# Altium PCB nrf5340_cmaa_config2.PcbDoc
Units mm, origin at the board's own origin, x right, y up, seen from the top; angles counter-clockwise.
Board outline 14 x 12 mm, 4 copper layers (Top Layer, Mid Layer 1, Mid Layer 2, Bottom Layer), stack 1.583 mm thick; 30 components, 69 nets, 170 pads, 84 vias.
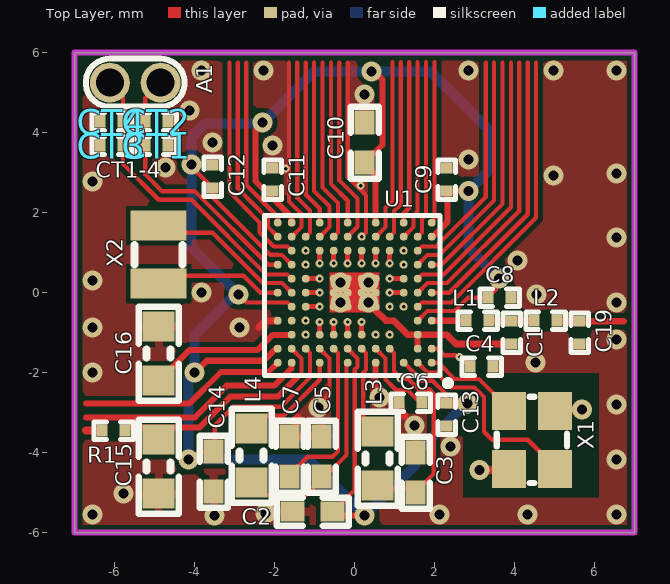
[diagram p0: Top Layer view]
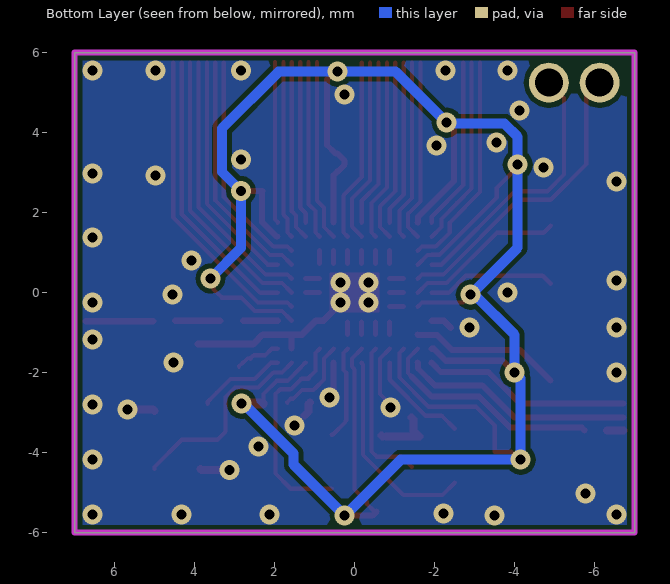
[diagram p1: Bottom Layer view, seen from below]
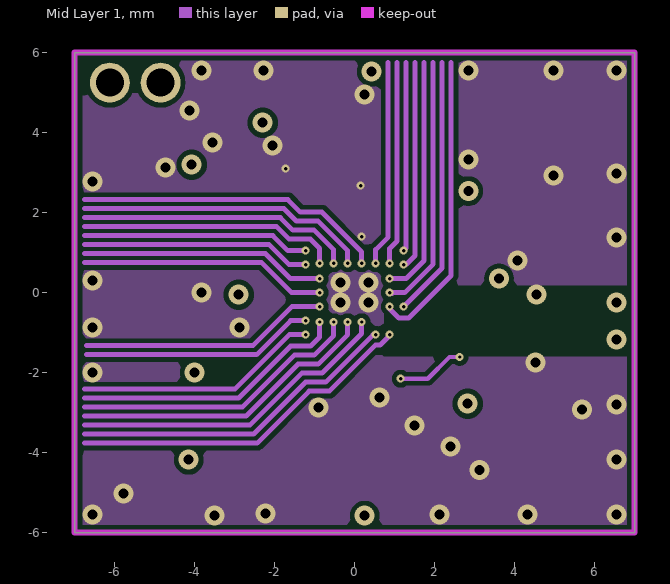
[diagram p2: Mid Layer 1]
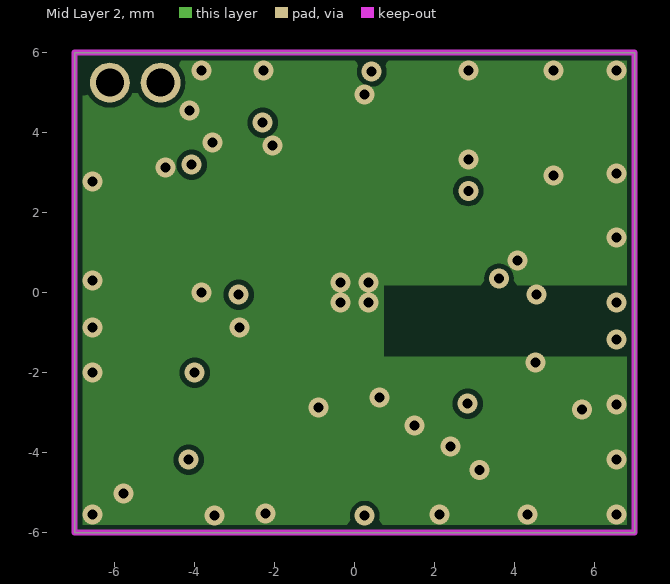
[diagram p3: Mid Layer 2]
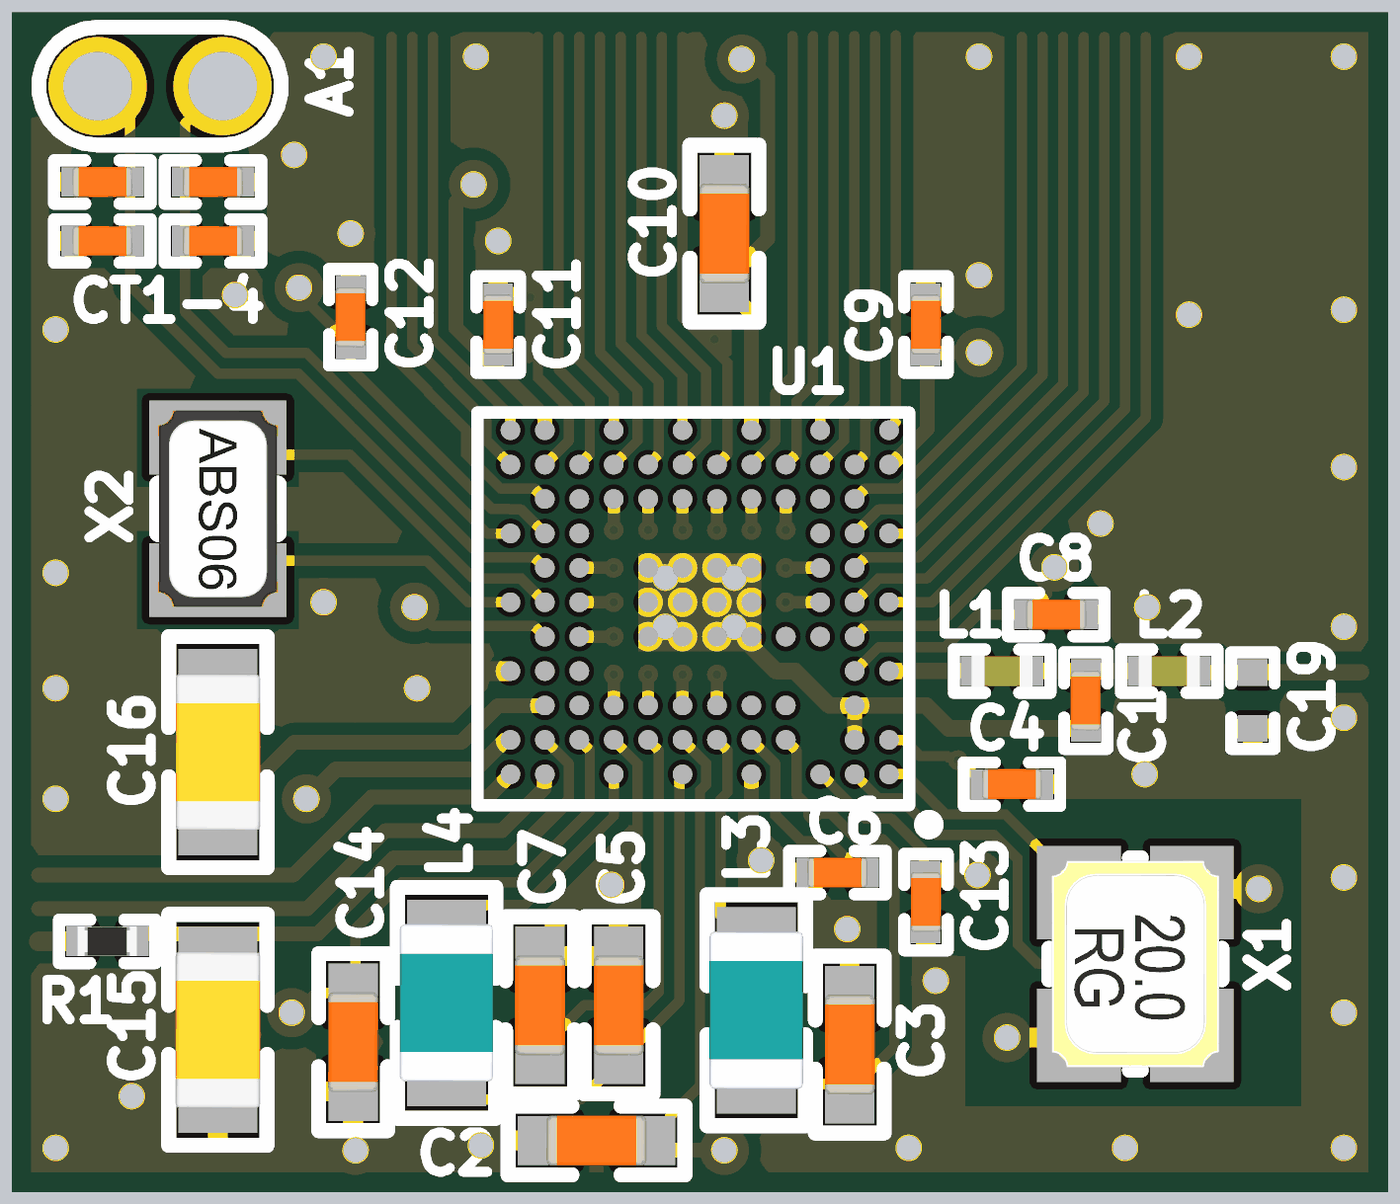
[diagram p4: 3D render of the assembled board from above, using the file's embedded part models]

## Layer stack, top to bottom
Top Solder: solder mask 0.0102, Solder Resist, Dk 3.5
Top Layer: signal copper 0.0356
Dielectric1: core 0.07, FR-4, Dk 4.8
Mid Layer 1: signal copper 0.036
Dielectric 3: prepreg 1.3, Dk 4.2
Mid Layer 2: signal copper 0.036
Dielectric 2: core 0.07, Dk 4.2
Bottom Layer: signal copper 0.0356
Bottom Solder: solder mask 0.0102, Solder Resist, Dk 3.5

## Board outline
-7,-6 7,-6 7,6 -7,6

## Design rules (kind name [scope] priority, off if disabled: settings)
Clearance Clearance_microvia [AsMM(ViaDiameter) = 0.3 vs AsMM(ViaDiameter) = 0.3] p1: gap=0.1 ignorepadtopadclearanceinfootprint=FALSE
Clearance Polygon_ANT [(InNamedPolygon('Top_Layer-GND')) or  (InNamedPolygon('Mid_Layer_1-GND')) or (InNamedPolygon('Mid_Layer_2-GND')) or (InNamedPolygon('Bottom_Layer-GND')) vs InNet('RF')] p2: gap=0.127 ignorepadtopadclearanceinfootprint=FALSE except(0: Arc-Hole Track-Hole SMDPad-Hole THPad-Hole Via-Hole Fill-Hole Poly-Hole Region-Hole Text-Hole)
Clearance Polygon [(InNamedPolygon('Top_Layer-GND')) or  (InNamedPolygon('Mid_Layer_1-GND')) or (InNamedPolygon('Mid_Layer_2-GND')) or (InNamedPolygon('Bottom_Layer-GND'))] p3: gap=0.125 ignorepadtopadclearanceinfootprint=FALSE
Clearance Clearance_Top [OnTopLayer] p4: gap=0.09 ignorepadtopadclearanceinfootprint=FALSE
Clearance [All] p5: gap=0.1 ignorepadtopadclearanceinfootprint=FALSE
ComponentClearance [All] p1 off: gap=0.254 collisioncheckmode=3 verticalgap=0.254 showdistances=FALSE
DiffPairsRouting [All] p1: maxlimit=0.193 minlimit=0.193 mostfreqgap=0.193 toplayer_minwidth=0.125 toplayer_maxwidth=0.381 toplayer_prefwidth=0.165 midlayer1_minwidth=0.125 midlayer1_maxwidth=0.381 midlayer1_prefwidth=0.165 midlayer2_minwidth=0.125 midlayer2_maxwidth=0.381 midlayer2_prefwidth=0.165 bottomlayer_minwidth=0.125 bottomlayer_maxwidth=0.381 bottomlayer_prefwidth=0.165 maxuncoupledlength=12.7
FabricationTestPointUsage TestPointUsage [All] p1: valid=0 allowmultiple=FALSE
FabricationTestpoint Testpoint [All] p1: side=3 testpointundercomponent=TRUE minsize=1.016 maxsize=2.54 preferedsize=1.524 minholesize=0 maxholesize=1.016 preferedholesize=0.813 testpointgrid=0.025 allowsidetop=TRUE allowsidebottom=TRUE usegrid=TRUE gridtolerance=0
Height [All] p1 off: minheight=0 maxheight=25.4 prefheight=12.7
HoleSize [All] p1: absolutevalues=TRUE maxlimit=4.064 minlimit=0.08 maxpercent=80.000 minpercent=20.000
MinimumAnnularRing [All] p1 off: minimumring=0.152
PolygonConnect PolygonConnect_1 [isVia and innet(gnd)] p1: connectstyle=Direct reliefconductorwidth=0.254 reliefentries=4 polygonreliefangle="90 Angle" airgapwidth=0.254
PolygonConnect [All] p2: connectstyle=Relief reliefconductorwidth=0.2 reliefentries=4 polygonreliefangle="90 Angle" airgapwidth=0.125
RoutingVias [All] p1: holewidth=0.1 width=0.25 viastyle="Through Hole" minholewidth=0.1 minwidth=0.25 maxholewidth=0.25 maxwidth=0.5 useviatemplates=TRUE viatemplateguid#1={ABB39D13-3140-4941-832D-BD17CF3CD9F1} viatemplateguid#2={15471998-75C1-4FB5-9936-6AB580A247F9} viatemplatename#1=v20h8m0 viatemplatename#2=v50h25m0mx0
SilkToSolderMaskClearance SilkscreenOverComponentPads [IsPad] p1: minsilkscreentomaskgap=0.254 clearancetoexposedcopper=TRUE
SolderMaskExpansion SolderMaskExpansion_via [isVia] p1: expansion=0.076 istentingtop=TRUE
SolderMaskExpansion [All] p2: expansion=0.076 istentingtop=FALSE
Width [All] p1: maxlimit=2 minlimit=0.105 preferedwidth=0.125 minimp=50.000000 maximp=50.000000 favimp=50.000000
23 further rules are at their usual default settings.

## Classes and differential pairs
differential pair D: +D_P -D_N

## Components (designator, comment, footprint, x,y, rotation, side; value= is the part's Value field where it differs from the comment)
A1 "NFC Antenna" TP_2x1mm_TH -5.488,5.25 r270 top
C1 "0.7pF" CAPC0603X03L_C#1 3.925,-1 r90 top
C2 "1.0µF" CAPC1005X04L -1.05,-5.475 r180 top
C3 "1.0µF" CAPC1005X04L 1.525,-4.5 r270 top
C4 "2.2nF" CAPC0603X03L_C#1 3.175,-1.85 r0 top
C5 "1.0µF" CAPC1005X04L -0.825,-4.1 r270 top
C6 "100nF" CAPC0603X03L_C#1 1.4,-2.75 r180 top
C7 "1.0µF" CAPC1005X04L -1.625,-4.1 r270 top
C8 "100nF" CAPC0603X03L_C#1 3.625,-0.125 r0 top
C9 "100nF" CAPC0603X03L_C#1 2.3,2.825 r90 top
C10 "1.0µF" CAPC1005X04L 0.25,3.75 r90 top
C11 "100nF" CAPC0603X03L_C#2 -2.05,2.825 r90 top
C12 "100nF" CAPC0603X03L_C#1 -3.55,2.9 r90 top
C13 "100nF" CAPC0603X03L_C#1 2.3,-3.05 r270 top
C14 "1.0µF" CAPC1005X04L -3.525,-4.475 r90 top
C15 "4.7µF" CAPC1608X06L -4.9,-4.35 r270 top
C16 "4.7µF" CAPC1608X06L -4.9,-1.525 r90 top
C19 "N.C." CAPC0603X03L_C_NC 5.625,-1 r90 top
CT1 "Antenna dependent" CAPC0603X03L_C#2 -4.95,3.675 r0 top
CT2 "Antenna dependent" CAPC0603X03L_C#2 -4.95,4.275 r0 top
CT3 "Antenna dependent" CAPC0603X03L_C#2 -6.075,3.675 r0 top
CT4 "Antenna dependent" CAPC0603X03L_C#2 -6.075,4.275 r0 top
L1 "2.2nH" INDC0603X03L_C 3.075,-0.7 r180 top
L2 "2.2nH" INDC0603X03L_C 4.775,-0.7 r180 top
L3 "10µH" INDC1608X06L 0.575,-4.15 r90 top
L4 "10µH" INDC1608X06L -2.575,-4.075 r90 top
R1 "2R2" RESC0603X03L_C -6.025,-3.45 r0 top
U1 "nRF5340-CMAA" BGA95C35P12X11_439X399X49 0,0 r180 top
X1 "32MHz" BT-XTAL_2016 4.43,-3.68 r270 top
X2 "32.768kHz" XTAL_2012 -4.9,0.95 r270 top

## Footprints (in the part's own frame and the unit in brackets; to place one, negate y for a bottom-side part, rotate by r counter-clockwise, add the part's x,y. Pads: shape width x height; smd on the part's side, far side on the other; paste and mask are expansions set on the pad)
BGA95C35P12X11_439X399X49 [mm] "BGA, 95-Leads, Body 4.39x3.99mmx0.49mm, Pitch 0.35mm"
  round 0.2 smd mask+0.05: A1(-1.925,1.75) A2(-1.575,1.75) A3(-1.225,1.75) A5(-0.525,1.75) A7(0.175,1.75) A9(0.875,1.75) A11(1.575,1.75) A12(1.925,1.75) B1(-1.925,1.4) B2(-1.575,1.4) B4(-0.875,1.4) B5(-0.525,1.4) B6(-0.175,1.4) B7(0.175,1.4) B8(0.525,1.4) B9(0.875,1.4) B10(1.225,1.4) B11(1.575,1.4) B12(1.925,1.4) C2(-1.575,1.05) C4(-0.875,1.05) C5(-0.525,1.05) C6(-0.175,1.05) C7(0.175,1.05) C8(0.525,1.05) C9(0.875,1.05) C10(1.225,1.05) C11(1.575,1.05) D1(-1.925,0.7) D2(-1.575,0.7) D10(1.225,0.7) D11(1.575,0.7) D12(1.925,0.7) E2(-1.575,0.35) E3(-1.225,0.35) E4(-0.875,0.35) E5(-0.525,0.35) E6(-0.175,0.35) E7(0.175,0.35) E8(0.525,0.35) E10(1.225,0.35) E11(1.575,0.35) F1(-1.925,0) F2(-1.575,0) F3(-1.225,0) F5(-0.525,0) F6(-0.175,0) F7(0.175,0) F8(0.525,0) F10(1.225,0) F11(1.575,0) F12(1.925,0) G2(-1.575,-0.35) G3(-1.225,-0.35) G5(-0.525,-0.35) G6(-0.175,-0.35) G7(0.175,-0.35) G8(0.525,-0.35) G10(1.225,-0.35) G11(1.575,-0.35) H1(-1.925,-0.7) H2(-1.575,-0.7) H3(-1.225,-0.7) H10(1.225,-0.7) H11(1.575,-0.7) H12(1.925,-0.7) J2(-1.575,-1.05) J3(-1.225,-1.05) J4(-0.875,-1.05) J5(-0.525,-1.05) J6(-0.175,-1.05) J7(0.175,-1.05) J8(0.525,-1.05) J9(0.875,-1.05) J10(1.225,-1.05) J11(1.575,-1.05) K1(-1.925,-1.4) K2(-1.575,-1.4) K3(-1.225,-1.4) K4(-0.875,-1.4) K5(-0.525,-1.4) K6(-0.175,-1.4) K7(0.175,-1.4) K8(0.525,-1.4) K9(0.875,-1.4) K10(1.225,-1.4) K11(1.575,-1.4) K12(1.925,-1.4) L1(-1.925,-1.75) L3(-1.225,-1.75) L5(-0.525,-1.75) L7(0.175,-1.75) L9(0.875,-1.75) L11(1.575,-1.75) L12(1.925,-1.75)
  silkscreen extent -2.38,-1.93 2.26,2.31, body extent -2.13,-1.93 2.26,2.06, height 0.41
BT-XTAL_2016 [mm] "Crystal 2.0 x 1.6 mm"
  rect 0.95x0.85 smd: 1(-0.725,-0.575) 2(0.725,-0.575) 3(0.725,0.575) 4(-0.725,0.575)
  silkscreen extent -1.08,-0.88 1.08,0.88, body extent -1.05,-0.85 1.05,0.85, height 0.56
CAPC0603X03L_C#1 [mm] "Chip Capacitor, 2-Leads, Body 0.6x0.3mm, IPC High Density"
  rect 0.27x0.3 smd: 1(-0.285,0) 2(0.285,0)
  silkscreen extent -0.49,-0.22 0.49,0.22, body extent -0.3,-0.15 0.31,0.15, height 0.3
CAPC0603X03L_C#2 [mm] "Chip Capacitor, 2-Leads, Body 0.6x0.3mm, IPC High Density"
  rect 0.27x0.3 smd mask+0.05: 1(-0.285,0) 2(0.285,0)
  silkscreen extent -0.49,-0.22 0.49,0.22, body extent -0.3,-0.15 0.31,0.15, height 0.3
CAPC0603X03L_C_NC [mm] "Chip Capacitor, 2-Leads, Body 0.6x0.3mm, IPC High Density"
  rect 0.27x0.3 smd mask+0.05: 1(-0.285,0) 2(0.285,0)
  silkscreen extent -0.49,-0.22 0.49,0.22
CAPC1005X04L [mm] "Chip Capacitor, 2-Leads, Body 1.0x0.5mm, IPC High Density"
  rect 0.6x0.5 smd: 1(-0.5,0) 2(0.5,0)
  silkscreen extent -0.9,-0.35 0.9,0.35, body extent -0.51,-0.25 0.51,0.25, height 0.5
CAPC1608X06L [mm] "Chip Capacitor, 2-Leads, Body 1.6x0.8mm, IPC High Density"
  rect 0.75x0.8 smd: 1(-0.675,0) 2(0.675,0)
  silkscreen extent -1.17,-0.5 1.17,0.5, body extent -0.8,-0.43 0.8,0.43, height 0.8
INDC0603X03L_C [mm] "Chip Inductor, 2-Leads, Body 0.6x0.3mm, IPC High Density"
  rect 0.27x0.3 smd: 1(-0.285,0) 2(0.285,0)
  silkscreen extent -0.49,-0.22 0.49,0.22, body extent -0.31,-0.16 0.31,0.16, height 0.26
INDC1608X06L [mm] "Chip Inductor, 2-Leads, Body 1.6x0.8mm, IPC High Density"
  rect 0.75x0.8 smd: 1(-0.675,0) 2(0.675,0)
  silkscreen extent -1.17,-0.5 1.17,0.5, body extent -0.8,-0.48 0.8,0.48, height 0.8
RESC0603X03L_C [mm] "Chip Resistor, 2-Leads, Body 0.6x0.3mm, IPC High Density"
  rect 0.27x0.3 smd: 1(-0.285,0) 2(0.285,0)
  silkscreen extent -0.49,-0.22 0.49,0.22, body extent -0.3,-0.15 0.3,0.15, height 0.23
TP_2x1mm_TH [mm]
  round 1 hole 0.7: 1(0,-0.635) 2(0,0.635)
  silkscreen extent -0.6,-1.23 0.6,1.23
XTAL_2012 [mm] "XTAL SMD 2.0 x 1.2 mm"
  rect 0.75x1.4 smd: 1(-0.725,0) 2(0.725,0)
  silkscreen extent -0.24,-0.6 0.24,0.6, body extent -1,-0.61 1,0.61, height 0.6

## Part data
A1: library part NFC_ANT_TP
C1: library part C0201-0.7p, "Capacitor, NP0, ±0.05pF"
C2 C3 C5 C7 C10 C14: library part C0402-1µ0-10V-X7S-GRM155C71A105KE11, "Capacitor, X7S, ±10%"
C4: library part C0201-2n2, "Capacitor, X7R, ±10%"
C6 C8 C9 C11 C12 C13: library part C0201-100n-16V-X7S, "Capacitor, X7S, ±10%"
C15: library part C0603-4µ7-10V-X7S, "Capacitor, X7S, ±10%"
C16: library part C0603-4µ7-6.3V-X7R, "Capacitor, X7R, ±10%"
C19: library part C0201-N.C., "Not mounted"
CT1 CT2 CT3 CT4: library part C0201-TBD, "Capacitor, NP0, ±5%"
L1 L2: library part L0201-2n2, "High frequency chip inductor, ±5%"
L3 L4: library part L0603-10µ, "Chip inductor, IDC,min = 50 mA, ±20%"
R1: library part R0201-2R2, "Resistor, ±1%, 0.05W"
U1: "Multi-protocol Bluetooth Low Energy, IEEE 802.15.4, ANT and 2.4GHz proprietary system-on-chip", Manufacturer="Nordic Semiconductor"
X1: library part XTAL_SMD2016_32MHz_8pF_General, "XTAL SMD 2016, 32MHz, Cl=8pF, Total Tol: ±30ppm"
X2: library part XTAL_SMD2012_32.768kHz_9pF_General, "XTAL SMD 2012, 32.768kHz, Cl=9pF, Total Tol: ±50ppm"

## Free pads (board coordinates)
  round 0.2 on Mech16: 1(-1.225,-1.05) 1(-1.225,-0.7) 1(-1.225,0.7) 1(-1.225,1.05) 1(0.175,1.4) 1(0.525,-1.05) 1(0.875,-1.05) 1(0.875,-0.35) 1(1.225,-0.35) 1(1.225,0.7) 1(1.225,1.05)
  round 0.5 on Mech16: 1(-0.35,-0.25) 1(-0.35,0.25) 1(0.35,0.25) 1(0.35,-0.25)

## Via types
v1: diameter 0.5, hole 0.25, Top Layer to Bottom Layer, tented both sides, 54 vias
v2: diameter 0.2, hole 0.08, Top Layer to Mid Layer 1, tented both sides, 30 vias

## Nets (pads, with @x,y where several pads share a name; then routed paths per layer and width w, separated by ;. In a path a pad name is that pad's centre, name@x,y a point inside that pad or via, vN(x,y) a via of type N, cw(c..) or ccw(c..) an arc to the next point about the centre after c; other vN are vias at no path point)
ANT: L1.2 U1.D1 | length 0.9
  Top Layer w0.165: U1.D1 L1.2@2.79,-0.7
D_N: U1.A11 | length 5.8
  Top Layer w0.15: -6.722,-3.118 -3.993,-3.118 -3.2,-2.325 -2.013,-2.325 -1.582,-1.894 -1.582,-1.771 -1.579,-1.768 -1.579,-1.754 U1.A11
D_P: U1.A12 | length 5.2
  Top Layer w0.15: -6.722,-2.775 -4.135,-2.775 -3.342,-1.982 -2.155,-1.982 -1.925,-1.752 U1.A12
GND: C1.1 C2.2 C3.1 C4.2 C5.1 C6.2 C7.1 C8.2 C9.2 C10.2 C11.2 C12.2 C13.2 C14.1 C15.2 C16.2 C19.1 CT1.2 CT2.2 CT3.1 CT4.1 U1.A5 U1.B2 U1.B9 U1.C2 U1.D12 U1.E5 U1.E6 U1.E7 U1.E8 U1.F5 U1.F6 U1.F7 U1.F8 U1.G5 U1.G6 U1.G7 U1.G8 U1.K6 U1.K11 X1.2 X1.4 | length 19.5
  Top Layer w0.105: -1.645,5.75 -1.645,2.284 -1.332,1.972 -1.332,1.643 U1.K11 ; v1@-0.9,-2.8 -0.632,-2.532 -0.632,-1.643 U1.B9 ; -0.175,5.75 -0.175,2.893 0.282,2.436 0.282,1.507 v2(0.175,1.4)
  Top Layer w0.15: v1@0.525,-2.515 U1.A5 ; U1.B2 U1.C2
  Top Layer w0.17: -2.4,-0.875 -2.225,-0.7 U1.D12 ; U1.E5 0.525,-0.445 0.78,-0.7 0.97,-0.7 1.32,-1.05 U1.C2 2.3,-1.05 2.535,-1.285 C1.1
  Top Layer w0.2: C7.1 -1.475,-3.45 -1.475,-3.175 -1.425,-3.125 ; C7.1@-1.6,-3.6 C5.1 C5.1@-0.8,-3.6 ; C5.1@-0.7,-3.6 C5.1@-0.675,-3.575 ; C6.2 1.15,-2.785 1.15,-2.975 1.25,-3.075 ; v1(3.125,-4.429) 3.832,-4.429 X1.2 ; X1.4 5.045,-2.915 v1(5.684,-2.915)
  other v1: -3.5,-5.575 -6.55,-5.55 2.125,-5.55 4.325,-5.55 6.55,-5.55 -2.225,-5.525 -5.775,-5.025 6.55,-4.175 2.4,-3.85 1.5,-3.325 -0.9,-2.875 6.55,-2.8 0.625,-2.625 -6.55,-2 4.525,-1.75 6.55,-1.175 -6.55,-0.875 -2.875,-0.875 -0.35,-0.25 0.35,-0.25 6.55,-0.25 4.55,-0.05 -3.825,0 -0.35,0.25 0.35,0.25 -6.55,0.3 4.075,0.8 6.55,1.375 -6.55,2.775 4.975,2.925 6.55,2.975 -4.725,3.125 2.84,3.325 -2.05,3.675 -3.55,3.75 -4.125,4.55 0.25,4.95 -3.825,5.55 -2.275,5.55 2.84,5.55 4.975,5.55 6.55,5.55
  other v2: 0.15,2.675 -1.725,3.1
NetC1_2: C1.2 L1.1 L2.2 | length 1.1
  Top Layer w0.165: L1.1 L2.2
NetC3_2: C3.2 C4.1 L3.1 U1.B1 U1.B4 | length 8.3
  Top Layer w0.105: L3.1@0.575,-4.9 1.6,-4.9 1.977,-4.523 1.977,-2.527 1.863,-2.413 1.598,-2.413 1.337,-2.152 v2@1.226,-2.152 ; U1.B4 0.982,-1.507 0.982,-1.775 0.982,-1.957 1.176,-2.15 1.224,-2.15 v2@1.226,-2.152 ; v2(1.15,-2.15) 1.152,-2.152 v2@1.226,-2.152 ; U1.B1 2.075,-1.4 2.24,-1.565 2.515,-1.565 2.529,-1.579 2.558,-1.579 2.6,-1.62 v2@2.6,-1.65 ; v2@2.683,-1.643 2.793,-1.753 2.808,-1.753 2.89,-1.835 C4.1
  Mid Layer 1 w0.105: v2(1.15,-2.15) 1.825,-2.15 2.369,-1.606 v2(2.625,-1.606)
NetC5_2: C5.2 L4.1 U1.A7 | length 5.2
  Top Layer w0.105: L4.1@-2.5,-4.75 -2.192,-5.058 -1.213,-5.058 -0.208,-4.052 -0.208,-1.8 -0.175,-1.768 U1.A7
NetC6_1: C6.1 U1.B5 | length 2
  Top Layer w0.105: U1.B5 0.768,-1.643 0.768,-2.167 0.988,-2.387 1.033,-2.432 1.321,-2.432 1.541,-2.653 1.602,-2.653 1.685,-2.735 C6.1
NetC7_2: C7.2 U1.B8 | length 3.8
  Top Layer w0.105: C7.2@-1.428,-4.353 -1.175,-4.1 -0.552,-4.1 -0.418,-3.965 -0.418,-1.507 U1.B8
NetC15_1: C15.1 R1.2 U1.B11 | length 5.7
  Top Layer w0.105: U1.B11 -1.332,-1.643 -1.332,-2.007 -1.425,-2.1
  Top Layer w0.15: R1.2 -5.74,-3.435 -5.68,-3.375 -5.665,-3.375 -5.663,-3.373 -3.885,-3.373 -3.112,-2.6 -1.925,-2.6 -1.425,-2.1
NetC16_1: C16.1 U1.C11 | length 3.8
  Top Layer w0.15: C16.1 -4.126,-1.426 -2.426,-1.426 -2.051,-1.051 U1.C11@-1.576,-1.051
NetL3_2: L3.2 U1.B6 | length 2.4
  Top Layer w0.105: U1.B6 0.282,-1.507 0.282,-1.932 0.213,-2.002 0.213,-3.188 0.227,-3.202 0.227,-3.227 0.55,-3.55 L3.2@0.575,-3.55
NetL4_2: L4.2 U1.A9 | length 2.6
  Top Layer w0.105: L4.2@-2.5,-3.4 -2.178,-3.077 -1.777,-3.077 -0.875,-2.176 U1.A9
P0.00/XL1: U1.F11 X2.1 | length 4
  Top Layer w0.105: X2.1 -4.725,1.5 -3.556,1.5 -2.298,0.243 -1.818,0.243 U1.F11
P0.01/XL2: U1.F12 X2.2 | length 3.2
  Top Layer w0.105: X2.2 -4.701,0.424 -2.776,0.424 -2.353,0 U1.F12
P0.02/NFC1: A1.1 CT3.2 CT4.2 U1.G11 | length 7.6
  Top Layer w0.105: A1.1 -5.79,4.917 CT4.2 CT3.2 -5.79,3.59 -5.79,3.215 -4.9,2.325 -4.084,2.325 -2.216,0.457 -2.025,0.457 -1.682,0.457 U1.G11
P0.03/NFC2: A1.2 CT1.1 CT2.1 U1.H12 | length 6.7
  Top Layer w0.105: A1.2 -5.235,4.868 CT2.1 CT1.1 -5.235,2.957 -4.813,2.535 -3.997,2.535 -2.162,0.7 U1.H12
P0.04/AIN0: U1.G10 | length 6.5
  Top Layer w0.125: U1.G10 v2(-0.875,0.35)
  Mid Layer 1 w0.125: -6.757,0.975 -2.232,0.975 -1.607,0.35 v2(-0.875,0.35)
P0.05/AIN1: U1.F10 | length 6.5
  Top Layer w0.125: U1.F10 v2(-0.875,0)
  Mid Layer 1 w0.125: -6.757,0.75 -2.325,0.75 -1.575,0 v2(-0.875,0)
P0.06/AIN2: U1.H10 | length 5.7
  Mid Layer 1 w0.125: -6.757,1.2 -2.139,1.2 -1.639,0.7 v2(-1.225,0.7)
P0.07/AIN3: U1.J10 | length 5.7
  Mid Layer 1 w0.125: -6.757,1.425 -2.045,1.425 -1.67,1.05 v2(-1.225,1.05)
P0.08/TRACEDATA3: U1.L12 | length 4.3
  Top Layer w0.105: -2.713,5.75 -2.713,2.694 -2.325,2.307 -2.325,2.3 -1.925,1.9 U1.L12
P0.09/TRACEDATA2: U1.J9 | length 6.8
  Top Layer w0.125: v2(-0.875,0.735) U1.J9
  Mid Layer 1 w0.125: -6.757,1.65 -1.952,1.65 -1.64,1.338 -1.106,1.338 -0.875,1.107 v2(-0.875,0.735)
P0.10/TRACEDATA1: U1.J8 | length 7.2
  Top Layer w0.125: v2(-0.525,0.735) U1.J8
  Mid Layer 1 w0.125: -6.757,1.875 -1.859,1.875 -1.547,1.563 -1.013,1.563 -0.525,1.075 v2(-0.525,0.735)
P0.11/TRACEDATA0: U1.J7 | length 7.6
  Top Layer w0.125: v2(-0.175,0.735) U1.J7
  Mid Layer 1 w0.125: -6.757,2.1 -1.766,2.1 -1.453,1.788 -0.912,1.788 -0.175,1.05 v2(-0.175,0.735)
P0.12/TRACECLK: U1.J6 | length 8.1
  Top Layer w0.125: v2(0.175,0.735) U1.J6
  Mid Layer 1 w0.125: -6.757,2.325 -1.673,2.325 -1.36,2.013 -0.819,2.013 0.175,1.018 v2(0.175,0.735)
P0.13/QSPI0: U1.K10 | length 4.5
  Top Layer w0.105: -1.435,5.75 -1.435,2.371 -1.118,2.054 -1.118,1.507 U1.K10
P0.14/QSPI1: U1.K9 | length 4.6
  Top Layer w0.105: -1.015,5.75 -1.015,2.545 -0.632,2.163 -0.632,1.643 U1.K9
P0.15/QSPI2: U1.L9 | length 4.1
  Top Layer w0.105: -1.225,5.75 -1.225,2.458 -0.875,2.108 U1.L9
P0.16/QSPI3: U1.K8 | length 4.6
  Top Layer w0.105: -0.805,5.75 -0.805,2.632 -0.418,2.245 -0.418,1.507 U1.K8
P0.17/QSPI_CLK: U1.L7 | length 4.2
  Top Layer w0.105: -0.595,5.75 -0.595,2.719 -0.175,2.299 U1.L7
P0.18/QSPI_CS: U1.K7 | length 4.6
  Top Layer w0.105: -0.385,5.75 -0.385,2.806 0.068,2.354 0.068,1.65 -0.175,1.407 U1.K7
P0.19: U1.J5 | length 5.5
  Top Layer w0.125: v2(0.525,0.735) U1.J5
  Mid Layer 1 w0.125: v2(0.525,0.735) 0.525,1.075 0.838,1.387 0.838,5.75
P0.20: U1.K5 | length 4.5
  Top Layer w0.105: U1.K5 0.768,1.643 0.768,2.123 0.943,2.298 0.943,5.759
P0.21: U1.J4 | length 5.4
  Top Layer w0.125: v2(0.875,0.735) U1.J4
  Mid Layer 1 w0.125: v2(0.875,0.735) 0.875,1.107 1.063,1.294 1.063,5.75
P0.22: U1.K4 | length 4.5
  Top Layer w0.105: U1.K4 0.982,1.507 0.982,2.041 1.153,2.211 1.153,5.759
P0.23: U1.H3 | length 5.2
  Mid Layer 1 w0.125: v2(1.225,0.7) 1.282,0.7 1.513,0.931 1.513,5.75
P0.24: U1.K2 | length 4.4
  Top Layer w0.105: U1.K2 1.682,1.507 1.682,1.85 1.783,1.95 1.783,5.759
P0.25/AIN4: U1.L1 | length 4
  Top Layer w0.105: U1.L1 1.925,1.768 1.993,1.835 1.993,5.765
P0.26/AIN5: U1.J2 | length 5.6
  Top Layer w0.105: U1.J2 1.682,1.157 2.036,1.157 3.275,2.396 3.275,5.75
P0.27/AIN6: U1.H1 | length 5.9
  Top Layer w0.105: U1.H1 2.173,0.7 3.695,2.222 3.695,5.75
P0.28/AIN7: U1.E3 | length 6.5
  Mid Layer 1 w0.125: v2(1.225,-0.35) 1.225,-0.343 2.188,0.62 2.188,5.75
P0.29: U1.E2 | length 7.8
  Top Layer w0.105: U1.E2 1.682,-0.243 2.418,-0.243 4.535,1.875 4.535,5.75
P0.30: U1.C4 | length 8.8
  Mid Layer 1 w0.125: -6.757,-3.762 -2.438,-3.762 -1.138,-2.463 -0.633,-2.463 0.517,-1.313 0.634,-1.313 0.875,-1.071 v2(0.875,-1.05)
P0.31: U1.C5 | length 8.3
  Mid Layer 1 w0.125: -6.757,-3.537 -2.531,-3.537 -1.231,-2.238 -0.726,-2.238 0.461,-1.05 v2(0.525,-1.05)
P1.00: U1.D10 | length 5.8
  Mid Layer 1 w0.125: -6.706,-1.55 -2.452,-1.55 -1.602,-0.7 v2(-1.225,-0.7)
P1.01: U1.E10 | length 6.6
  Top Layer w0.125: U1.E10 v2(-0.875,-0.35)
  Mid Layer 1 w0.125: -6.706,-1.325 -2.546,-1.325 -1.571,-0.35 v2(-0.875,-0.35)
P1.02/TWI: U1.J11 | length 5.5
  Top Layer w0.105: -3.133,5.75 -3.133,2.52 -2.769,2.157 -2.769,2.15 -2.378,1.759 -2.378,1.51 -2.025,1.157 -1.682,1.157 U1.J11
P1.03/TWI: U1.K12 | length 4.8
  Top Layer w0.105: -2.923,5.75 -2.923,2.607 -2.55,2.235 -2.55,2.228 -2.168,1.846 -2.168,1.643 U1.K12
P1.04: U1.K3 | length 4.5
  Top Layer w0.105: U1.K3 1.468,1.643 1.468,1.932 1.573,2.037 1.573,5.759
P1.05: U1.L3 | length 4.1
  Top Layer w0.105: U1.L3 1.225,1.987 1.363,2.124 1.363,5.759
P1.06: U1.J3 | length 4.7
  Mid Layer 1 w0.125: v2(1.225,1.05) 1.288,1.113 1.288,5.75
P1.07: U1.G3 | length 6.3
  Top Layer w0.125: v2(0.875,0.35) U1.G3
  Mid Layer 1 w0.125: v2(0.875,0.35) 1.282,0.35 1.738,0.806 1.738,5.75
P1.08: U1.F3 | length 6.8
  Top Layer w0.125: v2(0.875,0) U1.F3
  Mid Layer 1 w0.105: v2@0.91,0 v2@0.937,-0.028
  Mid Layer 1 w0.125: v2(0.875,0) 1.25,0 1.963,0.713 1.963,5.75
P1.09: U1.H2 | length 6
  Top Layer w0.105: U1.H2 1.818,0.943 2.118,0.943 3.485,2.309 3.485,5.75
P1.10: U1.E4 | length 7.5
  Mid Layer 1 w0.125: v2(0.875,-0.35) 0.875,-0.407 1.106,-0.638 1.344,-0.638 2.413,0.431 2.413,5.75
P1.11: U1.C6 | length 8.5
  Top Layer w0.125: U1.C6 v2(0.175,-0.735)
  Mid Layer 1 w0.125: -6.757,-3.312 -2.624,-3.312 -1.324,-2.013 -0.819,-2.013 0.175,-1.018 v2(0.175,-0.735)
P1.12: U1.C7 | length 8.1
  Top Layer w0.125: U1.C7 v2(-0.175,-0.735)
  Mid Layer 1 w0.125: -6.757,-3.087 -2.717,-3.087 -1.417,-1.788 -0.913,-1.788 -0.175,-1.05 v2(-0.175,-0.735)
P1.13: U1.C8 | length 7.6
  Top Layer w0.125: U1.C8 v2(-0.525,-0.735)
  Mid Layer 1 w0.125: -6.757,-2.862 -2.81,-2.862 -1.51,-1.563 -1.013,-1.563 -0.525,-1.075 v2(-0.525,-0.735)
P1.14: U1.C9 | length 7.2
  Top Layer w0.125: U1.C9 v2(-0.875,-0.735)
  Mid Layer 1 w0.125: -6.757,-2.637 -2.903,-2.637 -1.603,-1.338 -1.106,-1.338 -0.875,-1.107 v2(-0.875,-0.735)
P1.15: U1.C10 | length 6.1
  Mid Layer 1 w0.125: -6.757,-2.412 -2.997,-2.412 -1.634,-1.05 v2(-1.225,-1.05)
R\E\S\E\T\: U1.G2 | length 6.7
  Top Layer w0.105: U1.G2 1.682,0.457 2.227,0.457 3.905,2.135 3.905,5.75
RF: C19.2 L2.1 | length 1.7
  Top Layer w0.165: L2.1@5.042,-0.711 6.725,-0.711
SWDCLK: U1.F2 | length 7.1
  Top Layer w0.105: U1.F2 1.818,0.243 2.309,0.243 4.115,2.048 4.115,5.75
SWDIO: U1.F1 | length 7
  Top Layer w0.105: U1.F1 2.364,0 4.325,1.961 4.325,5.75
VBUS: R1.1 | length 0.4
  Top Layer w0.2: -6.72,-3.45 R1.1
VDD_NRF: C2.1 C8.1 C9.1 C10.1 C11.1 C12.1 C13.1 C14.2 U1.A3 U1.B7 U1.B10 U1.B12 U1.D2 U1.E11 U1.H11 U1.K1 U1.L5 U1.L11 | length 62.5
  Top Layer w0.105: v1(-4.15,-4.175) -4.106,-4.175 -3.906,-3.975 C14.2 ; v1(-4.075,3.2) -4.075,3.14 C12.1 -3.55,2.385 -2.112,0.947 -1.93,0.947 -1.925,0.943 -1.818,0.943 U1.H11 ; C14.2@-3.5,-3.975 -3.5,-3.317 -3.033,-2.85 -1.846,-2.85 -1.118,-2.121 -1.118,-1.507 U1.B10 ; v1(-2.9,-0.05) -2.707,-0.243 -1.682,-0.243 U1.E11 ; C2.1 -0.5,-5.475 -0.303,-5.278 -0.303,-5.228 0.002,-4.922 0.002,-1.915 0.068,-1.85 0.068,-1.643 U1.B7 ; U1.A3 1.238,-1.75 1.332,-1.844 1.332,-1.85 1.685,-2.203 1.949,-2.203 2.281,-2.534 2.281,-2.746 C13.1 ; U1.D2 1.818,-0.457 2.5,-0.457 2.83,-0.127 3.322,-0.127 3.322,-0.112 3.404,-0.03 3.419,-0.03 3.531,0.082 3.531,0.28 v1(3.607,0.356)
  Top Layer w0.15: v1(-2.3,4.25) -2.48,4.07 -2.48,2.79 -1.576,1.887 -1.576,1.751 U1.L11 ; C2.1 -0.45,-5.575 v1(0.25,-5.575) ; v1@0.5,5.525 0.692,5.332 0.692,3.693 0.475,3.475 0.425,3.475 0.25,3.3 C10.1 0.25,3.2 0.425,3.025 0.437,3.025 0.525,2.937 U1.L5 ; U1.K1 1.929,1.404 1.954,1.404 2.315,1.765 2.315,2.525 C9.1 v1(2.84,2.54)
  Top Layer w0.158: v1(-4,-2) -3.7,-1.7 -2.275,-1.7 -1.977,-1.402 -1.927,-1.402 U1.B12
  Top Layer w0.25: C13.1 2.31,-2.775 v1(2.825,-2.775)
  Bottom Layer w0.25: v1(2.825,-2.775) 2.775,-2.775 1.525,-4.025 1.525,-4.3 v1(0.25,-5.575) -1.15,-4.175 v1(-4.15,-4.175) -4.15,-2.15 v1(-4,-2) -4,-1.053 -2.997,-0.05 v1(-2.9,-0.05) -4.075,1.125 v1(-4.075,3.2) -4.075,3.897 -3.747,4.225 -2.325,4.225 v1(-2.3,4.25) -1.025,5.525 v1(0.425,5.525) 1.9,5.525 3.315,4.11 3.315,3.015 v1(2.84,2.54) 2.84,1.122 v1(3.607,0.356)
XC1: U1.A1 X1.1 | length 2.3
  Top Layer w0.105: U1.A1 2.091,-1.75 2.498,-2.158 2.925,-2.158 3.081,-2.158 3.107,-2.158 X1.1@3.452,-2.503 ; X1.1@3.675,-2.775 3.675,-2.725 X1.1@3.531,-2.581 ; X1.1@3.452,-2.503 X1.1@3.531,-2.581 ; X1.1@3.453,-2.503 X1.1@3.531,-2.581
XC2: U1.A2 X1.3 | length 5.1
  Top Layer w0.105: U1.A2 1.817,-1.993 2.036,-1.993 2.411,-2.368 2.85,-2.368 2.994,-2.368 3.232,-2.606 3.232,-3.476 3.432,-3.675 4.325,-3.675 5.005,-4.355 X1.3
pads on no net: U1.D11

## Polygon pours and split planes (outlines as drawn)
GND on Mid Layer 2 "Mid_Layer_2-GND" (solid, remove dead copper, pour order 1002): -15,15 -15,-15 12.5,-15 12.5,15
GND on Bottom Layer "Bottom_Layer-GND" (solid, remove dead copper, pour order 1001): -15,15 -15,-15 12.5,-15 12.5,15
GND on Mid Layer 1 "Mid_Layer_1-GND" (solid, remove dead copper, pour order 1004): -15,15 -15,-15 12.5,-15 12.5,15
GND on Top Layer "Top_Layer-GND" (solid, remove dead copper, pour order 1000): -15.274,14.151 -15.275,-15.849 12.225,-15.849 12.226,14.151

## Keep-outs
Keep-Out Layer:
  the board outline again, w0.15

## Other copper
Top Layer:
  rectangle net GND: -0.625,-0.5 0.625,0.5
  pour cut-out: 2.7,-2 2.7,-5.125 6.116,-5.125 6.116,-2
  pour cut-out: 3.72,-1.7 3.72,-1.545 4.2,-1.545 4.2,-0.975 2.025,-0.975 2.025,-1.7
  pour cut-out: 0.3,-1.8 0.3,-0.35 2.075,-0.35 2.075,-1.8
Mid Layer 1:
  pour cut-out: 0.725,-1.606 0.725,0.183 7,0.183 7,-1.606
Mid Layer 2:
  pour cut-out: 0.725,-1.606 0.725,0.183 7,0.183 7,-1.606

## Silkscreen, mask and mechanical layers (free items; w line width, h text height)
Top Overlay:
  text "CT1-4" at -6.475,2.875 h0.4
Mechanical 1:
  the board outline again, w0.15

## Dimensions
7,-6 to -7,-6 on Mechanical 3
7,-6 to 7,6 on Mechanical 3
